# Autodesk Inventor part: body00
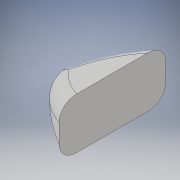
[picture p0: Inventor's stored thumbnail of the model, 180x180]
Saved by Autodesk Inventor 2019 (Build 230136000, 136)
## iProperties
Created: 2020-12
Part Number: body00
Material: 一般
Document SubType Name: Modeling
Designer: kikut
Density: 1 g/cm^3
Appearance: 既定
Author: kikut
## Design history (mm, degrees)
sketch "スケッチ1"
  geometry: L1 (-0.1, -0.02)-(0.1, -0.02); L2 (0.1, -0.02)-(0.1, 0.02); L3 (0.1, 0.02)-(-0.1, 0.02); L4 (-0.1, 0.02)-(-0.1, -0.02); L5 (-0.1, -0.02)-(0.1, 0.02); L6 (0.1, -0.02)-(-0.1, 0.02); 1 further point
  constraints: 12 end point, 2 midpoint, 2 parallel, 1 horizontal, 1 perpendicular
  dimensions: "d0" = 0.04 distance of L3.end L1.start; "d1" = 0.2 distance of L2.end L3.end
extrude "押し出し1" new body sketch "スケッチ1" stored distance "d2" = 0.06; taper "d3" = 0 deg
sketch "スケッチ2"
  geometry: L1 (0, -0.06)-(0, 0) reference; L2 (0.2, -0.06)-(0.2, 0) reference; L3 (0, 0)-(0.2, 0) reference; L4 (0.2, -0.06)-(0, -0.06) reference; L5 (0, -0.026)-(0, -0.032); L6 (0.194, -0.01)-(0.194, -0.013); L7 (0.194, -0.013)-(0.174, -0.033); L8 (0.174, -0.033)-(0.2, -0.058); L9 (-0.02, 0.02)-(0.22, 0.02); L10 (0.22, 0.02)-(0.22, -0.1); L11 (0.22, -0.1)-(-0.02, -0.1); L12 (-0.02, -0.1)-(-0.02, 0.02); 12 further points
  constraints: 16 end point, 4 point on line, 2 parallel, 2 vertical, 1 horizontal, 1 perpendicular, 14 other
  dimensions: "d4" = 0.032 distance from line of point (0.032, -0.012) L1; "d5" = 0.05 distance of point (0.032, -0.012) point (0.082, -0.011); "d6" = 0.05 horizontal distance of point (0.132, -0.017) point (0.082, -0.011); "d7" = 0.012 distance from line of point (0.032, -0.012) L3; "d8" = 0.011 distance from line of point (0.082, -0.011) L3; "d10" = 0.017 distance from line of point (0.132, -0.017) L3; "d11" = 0.026 distance from line of L5.start L3; "d12" = 0 distance from line of point (0.2, -0.06) L4; "d13" = 0.028 distance from line of L5.end L4; "d14" = 0.012 distance from line of point (0.028, -0.048) L4; "d15" = 0.01 distance from line of point (0.08, -0.05) L4; "d16" = 0.016 distance from line of point (0.13, -0.044) L4; "d17" = 0.028 distance from line of point (0.028, -0.048) L1; "d19" = 0.05 horizontal distance of point (0.13, -0.044) point (0.08, -0.05); "d20" = 0.08 distance from line of point (0.08, -0.05) L1; "d21" = 0.006 distance from line of L6.start L2; "d22" = 0.036 distance from line of point (0.164, -0.024) L2; "d23" = 0.024 distance from line of point (0.176, -0.02) L2; "d24" = 0.01 distance from line of L6.start L3; "d25" = 0.02 distance from line of point (0.176, -0.02) L3; "d26" = 0.024 distance from line of point (0.164, -0.024) L3; "d27" = 0.04 distance from line of point (0.16, -0.04) L2; "d28" = 0.025 distance from line of point (0.175, -0.048) L2; "d29" = 0.0125 distance from line of point (0.175, -0.048) L4; "d30" = 0.02 distance from line of L4 point (0.16, -0.04); "d31" = 0.003 distance of L6.start L6.end; "d32" = 0.033 distance from line of L7.end L3; "d33" = 0.026 distance from line of L7.end L2; "d34" = 0.002 distance of L8.end L2.start; "d35" = 0.12 distance of L11.end L9.start; "d36" = 0.24 distance of L10.end L11.end; "d37" = 0.02 distance between parallel lines of L1 L12; "d38" = 0.02 distance between parallel lines of L3 L9
extrude "押し出し2" cut sketch "スケッチ2" extent not by distance; stored distance "d39" = 0.02; taper "d40" = 0 deg
node "作業平面1"
sketch "スケッチ4"
  geometry: L1 (0.1, 0.02)-(0.1, -0.02) reference; L2 (-0.1, 0.002)-(-0.1, 0.057); L3 (-0.1, 0.057)-(0.1, 0.057); L4 (0.1, 0.057)-(0.1, 0.003); L5 (0.1, -0.003)-(0.1, -0.045); L6 (0.1, -0.045)-(-0.1, -0.045); L7 (-0.1, -0.045)-(-0.1, -0.002); L8 (-0.1, -0.02)-(-0.1, 0.02) reference; 7 further points
  constraints: 12 end point, 4 point on line, 2 perpendicular, 1 collinear, 1 parallel, 1 vertical, 10 other
  dimensions: "d42" = 0.002 vertical distance of point (0, 0) L2.start; "d43" = 0.01 vertical distance of point (-0.065, 0.01) point (0, 0); "d44" = 0.01 distance of point (0, 0.01) point (0, 0); "d46" = 0.003 vertical distance of L4.end point (0, 0); "d47" = 0.035 horizontal distance of point (-0.065, 0.01) L2.start; "d48" = 0.1 horizontal distance of point (0, 0.01) L2.start; "d49" = 0.16013 distance of point (0.06, 0.004) L2.start; "d50" = 0.004 vertical distance of point (0, 0) point (0.06, 0.004); "d51" = 0.004 distance of L7.end L2.start; "d52" = 0.02 distance of point (-0.065, -0.01) point (-0.065, 0.01); "d53" = 0.02 distance of point (0, -0.01) point (0, 0.01); "d54" = 0.008 distance of point (0.06, -0.004) point (0.06, 0.004); "d55" = 0.006 distance of L4.end L5.start; "d56" = 0.035 horizontal distance of point (-0.065, -0.01) L7.end; "d57" = 0.1 horizontal distance of point (0, -0.01) L7.end; "d58" = 0.16 distance of point (0.06, -0.004) L7.end
extrude "押し出し3" cut sketch "スケッチ4" extent not by distance; stored distance "d59" = 0.02; taper "d60" = 0 deg
sketch "スケッチ6" dims "d64" = 0.02, "d65" = 0.012
  geometry: L1 (0.026, 0.022)-(-0.034, 0.022); L2 (-0.034, 0.022)-(-0.034, -0.018); L3 (-0.034, -0.018)-(0.026, -0.018); L4 (0.026, -0.018)-(0.026, 0.022); 2 further points; 1 other entity
  constraints: 8 end point, 2 parallel, 1 coincident, 1 horizontal, 1 perpendicular, 2 other
  dimensions: "d66" = 0.04 distance of L3.end L1.start; "d67" = 0.06 distance of L1.start L1.end; "d68" = 0.02 distance from line of L3 point (-0.004, 0.002); "d69" = 0.03 distance from line of point (-0.004, 0.002) L4
extrude "押し出し4" cut sketch "スケッチ6" distance "d70" = 0.15; taper "d71" = 0 deg
fillet "フィレット1" dims "d72" = 0.004
fillet "フィレット2" dims "d73" = 0.004
fillet "フィレット3" dims "d74" = 0.002
sketch "スケッチ7"
  geometry: L1 (0.09, -0.04)-(-0.1, -0.04); L2 (-0.1, -0.04)-(-0.1, 0.04); L3 (-0.1, 0.04)-(0.09, 0.04); L4 (0.09, 0.04)-(0.09, -0.04); L5 (0.152, 0)-(-0.199, 0) reference; 1 further point
  constraints: 8 end point, 2 parallel, 1 horizontal, 1 perpendicular, 1 other
  dimensions: "d83" = 0.08 distance of L1.end L2.end; "d84" = 0.1 distance from line of L2 point (0, 0); "d85" = 0.19 distance of L2.end L3.end
extrude "押し出し5" cut sketch "スケッチ7" stored distance "d86" = 10; taper "d87" = 0 deg
node "ソリッド1"
other parameters: "d41" = 0.1
